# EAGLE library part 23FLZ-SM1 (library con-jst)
CONNECTOR
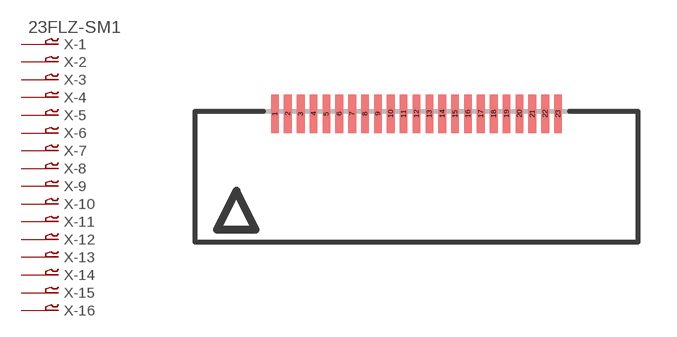
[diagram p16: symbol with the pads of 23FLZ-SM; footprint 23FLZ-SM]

Designator prefix X; gates -1=P-VN -2=P-N -3=P-N -4=P-N -5=P-N -6=P-N -7=P-N -8=P-N -9=P-N -10=P-N -11=P-N -12=P-N -13=P-N -14=P-N -15=P-N -16=P-N -17=P-N -18=P-N -19=P-N -20=P-N -21=P-N -22=P-N -23=P-N

## 23FLZ-SM1 (OC_FARNELL: unknown; OC_NEWARK: unknown)  [23FLZ-SM]
1  -1:1  pas
2  -2:1  pas
3  -3:1  pas
4  -4:1  pas
5  -5:1  pas
6  -6:1  pas
7  -7:1  pas
8  -8:1  pas
9  -9:1  pas
10  -10:1  pas
11  -11:1  pas
12  -12:1  pas
13  -13:1  pas
14  -14:1  pas
15  -15:1  pas
16  -16:1  pas
17  -17:1  pas
18  -18:1  pas
19  -19:1  pas
20  -20:1  pas
21  -21:1  pas
22  -22:1  pas
23  -23:1  pas

## Footprint 23FLZ-SM (pad centres in mm)
CONNECTOR
smd 0.3 x 1.5: 1 -5.5,2.5; 2 -5,2.5; 3 -4.5,2.5; 4 -4,2.5; 5 -3.5,2.5; 6 -3,2.5; 7 -2.5,2.5; 8 -2,2.5; 9 -1.5,2.5; 10 -1,2.5; 11 -0.5,2.5; 12 0,2.5; 13 0.5,2.5; 14 1,2.5; 15 1.5,2.5; 16 2,2.5; 17 2.5,2.5; 18 3,2.5; 19 3.5,2.5; 20 4,2.5; 21 4.5,2.5; 22 5,2.5; 23 5.5,2.5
